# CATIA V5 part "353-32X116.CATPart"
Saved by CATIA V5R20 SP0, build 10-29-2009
Part number: 353-32X116
Definition: NONE
Nomenclature: 353-32X116
Source: Unknown
Description: 353-32X116
Bounding box of the stored display mesh (mm): x -7 to 109, y -22.5 to 22.5, z -22.5 to 22.5
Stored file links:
  C:\Users\Utente\Desktop\IO LAVORO\3D X SITO CF\X SITO\PLASTICA\353\353-32X116.CATPart
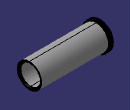
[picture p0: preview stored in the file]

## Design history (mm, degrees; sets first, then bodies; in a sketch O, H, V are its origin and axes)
Body1 "353-32X116" (main body)
  Solid1: solid without history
